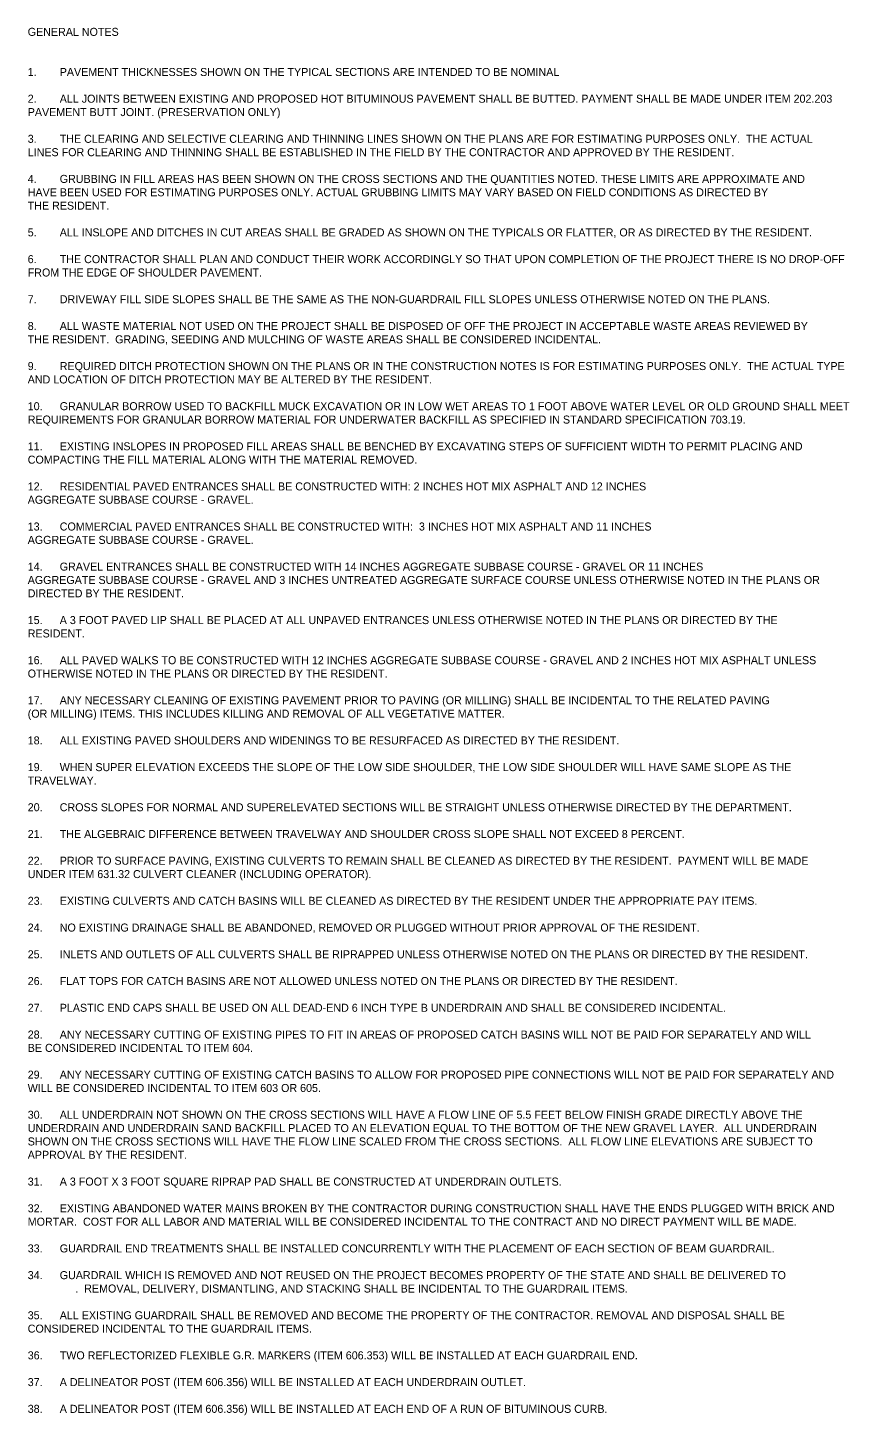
# Model space of a CAD drawing. Extents: x -831 to 3331, y -1004 to 250.
# Drawn here: x -831 to -523, y -313 to 207 of the extents above; entities that cross this region are included whole.
import ezdxf

# ---------------------------------------------------------------- set-up
doc = ezdxf.new("R2010")
doc.units = 0
doc.layers.add('Default', color=7, linetype='Continuous')

msp = doc.modelspace()

# ---------------------------------------------------------------- texts
at = {"layer": 'Default'}
for s, height, p in [('GENERAL NOTES', 3, (-830.7, 204.25)), ('1.', 3, (-830.7, 189.22)), ('PAVEMENT THICKNESSES SHOWN ON THE TYPICAL SECTIONS ARE INTENDED TO BE NOMINAL', 3, (-818.7, 189.22)), ('2.', 3, (-830.7, 179.2)), ('ALL JOINTS BETWEEN EXISTING AND PROPOSED HOT BITUMINOUS PAVEMENT SHALL BE BUTTED. PAYMENT SHALL BE MADE UNDER ITEM 202.203', 2.99999, (-818.7, 179.2)), ('PAVEMENT BUTT JOINT. (PRESERVATION ONLY)', 3, (-830.7, 174.19)), ('3.', 3, (-830.7, 164.17)), ('THE CLEARING AND SELECTIVE CLEARING AND THINNING LINES SHOWN ON THE PLANS ARE FOR ESTIMATING PURPOSES ONLY.  THE ACTUAL ', 2.99999, (-818.7, 164.17)), ('LINES FOR CLEARING AND THINNING SHALL BE ESTABLISHED IN THE FIELD BY THE CONTRACTOR AND APPROVED BY THE RESIDENT.', 2.99999, (-830.7, 159.16)), ('4.', 3, (-830.7, 149.14)), ('GRUBBING IN FILL AREAS HAS BEEN SHOWN ON THE CROSS SECTIONS AND THE QUANTITIES NOTED. THESE LIMITS ARE APPROXIMATE AND', 2.99999, (-818.7, 149.14)), ('HAVE BEEN USED FOR ESTIMATING PURPOSES ONLY. ACTUAL GRUBBING LIMITS MAY VARY BASED ON FIELD CONDITIONS AS DIRECTED BY ', 2.99999, (-830.7, 144.13)), ('THE RESIDENT. ', 3, (-830.7, 139.12)), ('5.', 3, (-830.7, 129.1)), ('ALL INSLOPE AND DITCHES IN CUT AREAS SHALL BE GRADED AS SHOWN ON THE TYPICALS OR FLATTER, OR AS DIRECTED BY THE RESIDENT.', 2.99999, (-818.7, 129.1)), ('6.', 3, (-830.7, 119.08)), ('THE CONTRACTOR SHALL PLAN AND CONDUCT THEIR WORK ACCORDINGLY SO THAT UPON COMPLETION OF THE PROJECT THERE IS NO DROP-OFF ', 2.99999, (-818.7, 119.08)), ('FROM THE EDGE OF SHOULDER PAVEMENT. ', 3, (-830.7, 114.07)), ('7.', 3, (-830.7, 104.05)), ('DRIVEWAY FILL SIDE SLOPES SHALL BE THE SAME AS THE NON-GUARDRAIL FILL SLOPES UNLESS OTHERWISE NOTED ON THE PLANS.', 2.99999, (-818.7, 104.05)), ('8.', 3, (-830.7, 94.03)), ('ALL WASTE MATERIAL NOT USED ON THE PROJECT SHALL BE DISPOSED OF OFF THE PROJECT IN ACCEPTABLE WASTE AREAS REVIEWED BY ', 2.99999, (-818.7, 94.03)), ('THE RESIDENT.  GRADING, SEEDING AND MULCHING OF WASTE AREAS SHALL BE CONSIDERED INCIDENTAL.', 3, (-830.7, 89.02)), ('9.', 3, (-830.7, 79)), ('REQUIRED DITCH PROTECTION SHOWN ON THE PLANS OR IN THE CONSTRUCTION NOTES IS FOR ESTIMATING PURPOSES ONLY.  THE ACTUAL TYPE ', 2.99999, (-818.7, 79)), ('AND LOCATION OF DITCH PROTECTION MAY BE ALTERED BY THE RESIDENT.', 3, (-830.7, 73.99)), ('10.', 3, (-830.7, 63.97)), ('GRANULAR BORROW USED TO BACKFILL MUCK EXCAVATION OR IN LOW WET AREAS TO 1 FOOT ABOVE WATER LEVEL OR OLD GROUND SHALL MEET ', 2.99999, (-818.7, 63.97)), ('REQUIREMENTS FOR GRANULAR BORROW MATERIAL FOR UNDERWATER BACKFILL AS SPECIFIED IN STANDARD SPECIFICATION 703.19.', 2.99999, (-830.7, 58.96)), ('COMPACTING THE FILL MATERIAL ALONG WITH THE MATERIAL REMOVED.', 3, (-830.7, 43.93)), ('11.', 3, (-830.7, 48.94)), ('EXISTING INSLOPES IN PROPOSED FILL AREAS SHALL BE BENCHED BY EXCAVATING STEPS OF SUFFICIENT WIDTH TO PERMIT PLACING AND ', 2.99999, (-818.7, 48.94)), ('12.', 3, (-830.7, 33.91)), ('RESIDENTIAL PAVED ENTRANCES SHALL BE CONSTRUCTED WITH: 2 INCHES HOT MIX ASPHALT AND 12 INCHES ', 3, (-818.7, 33.91)), ('AGGREGATE SUBBASE COURSE - GRAVEL.', 3, (-830.7, 28.9)), ('13.', 3, (-830.7, 18.88)), ('COMMERCIAL PAVED ENTRANCES SHALL BE CONSTRUCTED WITH:  3 INCHES HOT MIX ASPHALT AND 11 INCHES ', 3, (-818.7, 18.88)), ('AGGREGATE SUBBASE COURSE - GRAVEL.', 3, (-830.7, 13.87)), ('14.', 3, (-830.7, 3.85)), ('GRAVEL ENTRANCES SHALL BE CONSTRUCTED WITH 14 INCHES AGGREGATE SUBBASE COURSE - GRAVEL OR 11 INCHES ', 3, (-818.7, 3.85)), ('AGGREGATE SUBBASE COURSE - GRAVEL AND 3 INCHES UNTREATED AGGREGATE SURFACE COURSE UNLESS OTHERWISE NOTED IN THE PLANS OR ', 2.99999, (-830.7, -1.16)), ('DIRECTED BY THE RESIDENT.', 3, (-830.7, -6.17)), ('15.', 3, (-830.7, -16.19)), ('A 3 FOOT PAVED LIP SHALL BE PLACED AT ALL UNPAVED ENTRANCES UNLESS OTHERWISE NOTED IN THE PLANS OR DIRECTED BY THE ', 2.99999, (-818.7, -16.19)), ('RESIDENT.', 3, (-830.7, -21.2)), ('16.', 3, (-830.7, -31.22)), ('ALL PAVED WALKS TO BE CONSTRUCTED WITH 12 INCHES AGGREGATE SUBBASE COURSE - GRAVEL AND 2 INCHES HOT MIX ASPHALT UNLESS ', 2.99999, (-818.7, -31.22)), ('OTHERWISE NOTED IN THE PLANS OR DIRECTED BY THE RESIDENT.', 3, (-830.7, -36.23)), ('17.', 3, (-830.7, -46.25)), ('ANY NECESSARY CLEANING OF EXISTING PAVEMENT PRIOR TO PAVING (OR MILLING) SHALL BE INCIDENTAL TO THE RELATED PAVING ', 2.99999, (-818.7, -46.25)), ('(OR MILLING) ITEMS. THIS INCLUDES KILLING AND REMOVAL OF ALL VEGETATIVE MATTER.', 3, (-830.7, -51.26)), ('18.', 3, (-830.7, -61.28)), ('ALL EXISTING PAVED SHOULDERS AND WIDENINGS TO BE RESURFACED AS DIRECTED BY THE RESIDENT.', 3, (-818.7, -61.28)), ('19.', 3, (-830.7, -71.3)), ('WHEN SUPER ELEVATION EXCEEDS THE SLOPE OF THE LOW SIDE SHOULDER, THE LOW SIDE SHOULDER WILL HAVE SAME SLOPE AS THE ', 2.99999, (-818.7, -71.3)), ('TRAVELWAY.', 3, (-830.7, -76.31)), ('20.', 3, (-830.7, -86.33)), ('CROSS SLOPES FOR NORMAL AND SUPERELEVATED SECTIONS WILL BE STRAIGHT UNLESS OTHERWISE DIRECTED BY THE DEPARTMENT.', 2.99999, (-818.7, -86.33)), ('21.', 3, (-830.7, -96.35)), ('THE ALGEBRAIC DIFFERENCE BETWEEN TRAVELWAY AND SHOULDER CROSS SLOPE SHALL NOT EXCEED 8 PERCENT.', 3, (-818.7, -96.35)), ('22.', 3, (-830.7, -106.37)), ('PRIOR TO SURFACE PAVING, EXISTING CULVERTS TO REMAIN SHALL BE CLEANED AS DIRECTED BY THE RESIDENT.  PAYMENT WILL BE MADE ', 2.99999, (-818.7, -106.37)), ('UNDER ITEM 631.32 CULVERT CLEANER (INCLUDING OPERATOR).', 3, (-830.7, -111.38)), ('23.', 3, (-830.7, -121.4)), ('EXISTING CULVERTS AND CATCH BASINS WILL BE CLEANED AS DIRECTED BY THE RESIDENT UNDER THE APPROPRIATE PAY ITEMS.', 2.99999, (-818.7, -121.4)), ('24.', 3, (-830.7, -131.42)), ('NO EXISTING DRAINAGE SHALL BE ABANDONED, REMOVED OR PLUGGED WITHOUT PRIOR APPROVAL OF THE RESIDENT.', 3, (-818.7, -131.42)), ('25.', 3, (-830.7, -141.44)), ('INLETS AND OUTLETS OF ALL CULVERTS SHALL BE RIPRAPPED UNLESS OTHERWISE NOTED ON THE PLANS OR DIRECTED BY THE RESIDENT.', 2.99999, (-818.7, -141.44)), ('26.', 3, (-830.7, -151.46)), ('FLAT TOPS FOR CATCH BASINS ARE NOT ALLOWED UNLESS NOTED ON THE PLANS OR DIRECTED BY THE RESIDENT.', 3, (-818.7, -151.46)), ('27.', 3, (-830.7, -161.48)), ('PLASTIC END CAPS SHALL BE USED ON ALL DEAD-END 6 INCH TYPE B UNDERDRAIN AND SHALL BE CONSIDERED INCIDENTAL.', 2.99999, (-818.7, -161.48)), ('28.', 3, (-830.7, -171.5)), ('ANY NECESSARY CUTTING OF EXISTING PIPES TO FIT IN AREAS OF PROPOSED CATCH BASINS WILL NOT BE PAID FOR SEPARATELY AND WILL ', 2.99999, (-818.7, -171.5)), ('BE CONSIDERED INCIDENTAL TO ITEM 604.', 3, (-830.7, -176.51)), ('29.', 3, (-830.7, -186.53)), ('ANY NECESSARY CUTTING OF EXISTING CATCH BASINS TO ALLOW FOR PROPOSED PIPE CONNECTIONS WILL NOT BE PAID FOR SEPARATELY AND ', 2.99999, (-818.7, -186.53)), ('WILL BE CONSIDERED INCIDENTAL TO ITEM 603 OR 605.', 3, (-830.7, -191.54)), ('30.', 3, (-830.7, -201.56)), ('ALL UNDERDRAIN NOT SHOWN ON THE CROSS SECTIONS WILL HAVE A FLOW LINE OF 5.5 FEET BELOW FINISH GRADE DIRECTLY ABOVE THE ', 2.99999, (-818.7, -201.56)), ('UNDERDRAIN AND UNDERDRAIN SAND BACKFILL PLACED TO AN ELEVATION EQUAL TO THE BOTTOM OF THE NEW GRAVEL LAYER.  ALL UNDERDRAIN ', 2.99999, (-830.7, -206.57)), ('SHOWN ON THE CROSS SECTIONS WILL HAVE THE FLOW LINE SCALED FROM THE CROSS SECTIONS.  ALL FLOW LINE ELEVATIONS ARE SUBJECT TO ', 2.99999, (-830.7, -211.58)), ('APPROVAL BY THE RESIDENT.  ', 3, (-830.7, -216.59)), ('31.', 3, (-830.7, -226.61)), ('A 3 FOOT X 3 FOOT SQUARE RIPRAP PAD SHALL BE CONSTRUCTED AT UNDERDRAIN OUTLETS.', 3, (-818.7, -226.61)), ('32.', 3, (-830.7, -236.63)), ('EXISTING ABANDONED WATER MAINS BROKEN BY THE CONTRACTOR DURING CONSTRUCTION SHALL HAVE THE ENDS PLUGGED WITH BRICK AND ', 2.99999, (-818.7, -236.63)), ('MORTAR.  COST FOR ALL LABOR AND MATERIAL WILL BE CONSIDERED INCIDENTAL TO THE CONTRACT AND NO DIRECT PAYMENT WILL BE MADE.', 2.99999, (-830.7, -241.64)), ('33.', 3, (-830.7, -251.66)), ('GUARDRAIL END TREATMENTS SHALL BE INSTALLED CONCURRENTLY WITH THE PLACEMENT OF EACH SECTION OF BEAM GUARDRAIL.', 2.99999, (-818.7, -251.66)), ('34.', 3, (-830.7, -261.68)), ('GUARDRAIL WHICH IS REMOVED AND NOT REUSED ON THE PROJECT BECOMES PROPERTY OF THE STATE AND SHALL BE DELIVERED TO ', 2.99999, (-818.7, -261.68)), ('                .  REMOVAL, DELIVERY, DISMANTLING, AND STACKING SHALL BE INCIDENTAL TO THE GUARDRAIL ITEMS.', 2.99999, (-830.7, -266.69)), ('35.', 3, (-830.7, -276.71)), ('ALL EXISTING GUARDRAIL SHALL BE REMOVED AND BECOME THE PROPERTY OF THE CONTRACTOR. REMOVAL AND DISPOSAL SHALL BE ', 2.99999, (-818.7, -276.71)), ('CONSIDERED INCIDENTAL TO THE GUARDRAIL ITEMS.', 3, (-830.7, -281.72)), ('36.', 3, (-830.7, -291.74)), ('TWO REFLECTORIZED FLEXIBLE G.R. MARKERS (ITEM 606.353) WILL BE INSTALLED AT EACH GUARDRAIL END.  ', 3, (-818.7, -291.74)), ('37.', 3, (-830.7, -301.76)), ('A DELINEATOR POST (ITEM 606.356) WILL BE INSTALLED AT EACH UNDERDRAIN OUTLET.', 3, (-818.7, -301.76)), ('38.', 3, (-830.7, -311.78)), ('A DELINEATOR POST (ITEM 606.356) WILL BE INSTALLED AT EACH END OF A RUN OF BITUMINOUS CURB.', 3, (-818.7, -311.78))]:
    msp.add_text(s, height=height, dxfattribs=at).set_placement(p)

doc.saveas('drawing.dxf')
